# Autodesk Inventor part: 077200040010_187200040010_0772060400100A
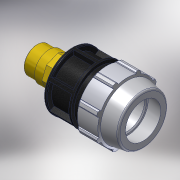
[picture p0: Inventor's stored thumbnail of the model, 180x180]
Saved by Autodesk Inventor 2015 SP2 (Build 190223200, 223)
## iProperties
Created: 2017-02
Part Number: 077200040010_187200040010_0772060400100A
Material: PVC-Piping
Description: PLASSON MALE ADAPTOR INTEGRAL BRASS THREAD 40-1"
Document SubType Name: Modeling
Designer: KIM
Mass: 92.6774 g
Surface Area: 199.44 cm^2
Volume: 66.1981 cm^3
Density: 1.4 g/cm^3
Appearance: PTFE
Author: KIM
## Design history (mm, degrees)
derived "07720.ipt"
feature "Solid1::07720.ipt"
tag "TaggingFeature1"
body "Solid1"
other parameters: "d4" = 21.57143, "d5" = 21.57143, "d7" = 82, "d8" = 61.5, "d9" = 21.57143, "d11" = 4.31429, "d12" = 65.6, "d13" = 120 deg, "d15" = 10 deg, "d16" = 73.8, "d18" = 2, "d19" = 35 deg, "d20" = 17.5 deg, "d21" = 76.26, "d23" = 0, "d25" = 360 deg, "d27" = 1.64, "d34" = 4.1, "d36" = 0, "d42" = 30.2, "d43" = 2.46, "d46" = 1.2, "d49" = 91, "d51" = 151, "d53" = 0.8, "d55" = 360 deg, "d59" = 30.2, "d60" = 33.249, "d61" = 36.5739, "d63" = 50.33333, "d64" = 23.2743, "d65" = 151, "d66" = 17.04822, "d67" = 0, "d68" = 0.8, "d71" = 30 deg, "d72" = 29.9241, "E_" = 82, "H_" = 151, "l_" = 91, "R_" = 33.249, "d73" = 28.4137
